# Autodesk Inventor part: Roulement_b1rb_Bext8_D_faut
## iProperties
Created: 2011-10
Part Number: Roulement_b1rb_Bext8_D_faut
Document SubType Name: Modeling
Designer: Bruno
Author: Bruno
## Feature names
1. Base1
